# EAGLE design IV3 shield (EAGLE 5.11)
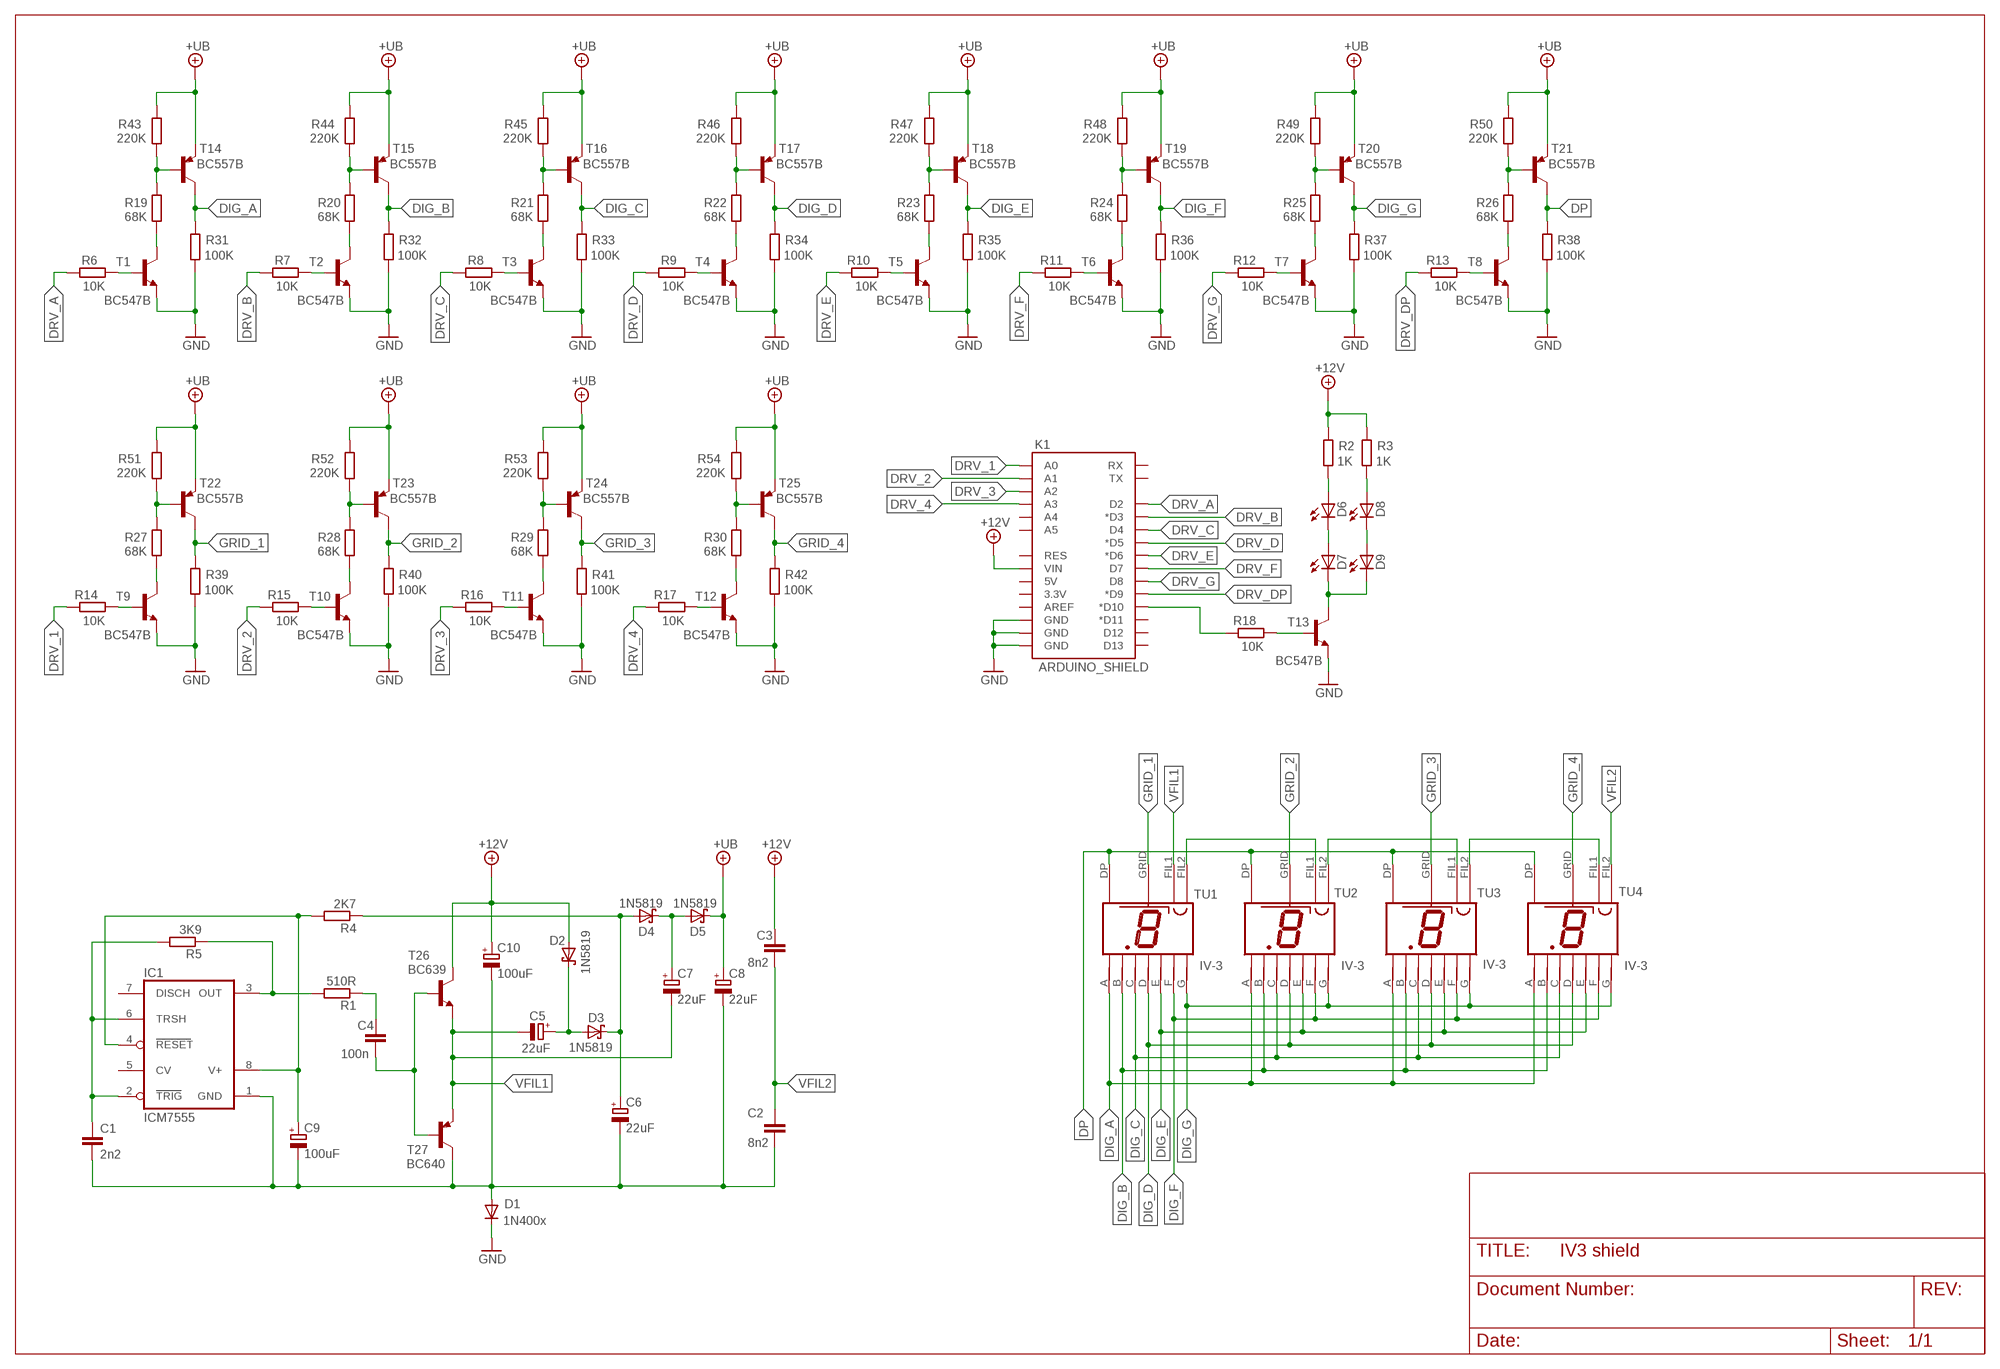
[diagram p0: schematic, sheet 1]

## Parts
C1  2n2  C5/2.5  [C5B2.5]
C2  8n2  C5/2.5  [C5B2.5]
C3  8n2  C5/2.5  [C5B2.5]
C4  100n  C5/2.5  [C5B2.5]
C5  22uF  CPOL-EUE2-4H  [E2-4H]
C6  22uF  CPOL-EUE2-4H  [E2-4H]
C7  22uF  CPOL-EUE2-4H  [E2-4H]
C8  22uF  CPOL-EUE2-4H  [E2-4H]
C9  100uF  CPOL-EUE2,5-6H  [E2,5-6H]
C10  100uF  CPOL-EUE2,5-6H  [E2,5-6H]
D1  1N400x  1N4004DO41-7.6  [DO41-7.6]
D2  1N5819  1N5819-B  [DO41-7.6]
D3  1N5819  1N5819-B  [DO41-7.6]
D4  1N5819  1N5819-B  [DO41-7.6]
D5  1N5819  1N5819-B  [DO41-7.6]
D6  LED3MM  [LED3MM]
D7  LED3MM  [LED3MM]
D8  LED3MM  [LED3MM]
D9  LED3MM  [LED3MM]
IC1  ICM7555  [DIL08]
K1  ARDUINO_SHIELD  ARDUINO_SHIELDNO_SILK  [DUEMILANOVE_VIAS]
R1  510R  R-EU_0207/2V  [0207/2V]
R2  1K  R-EU_0207/2V  [0207/2V]
R3  1K  R-EU_0207/2V  [0207/2V]
R4  2K7  R-EU_0207/2V  [0207/2V]
R5  3K9  R-EU_0207/2V  [0207/2V]
R6  10K  R-EU_0207/2V  [0207/2V]
R7  10K  R-EU_0207/2V  [0207/2V]
R8  10K  R-EU_0207/2V  [0207/2V]
R9  10K  R-EU_0207/2V  [0207/2V]
R10  10K  R-EU_0207/2V  [0207/2V]
R11  10K  R-EU_0207/2V  [0207/2V]
R12  10K  R-EU_0207/2V  [0207/2V]
R13  10K  R-EU_0207/2V  [0207/2V]
R14  10K  R-EU_0207/2V  [0207/2V]
R15  10K  R-EU_0207/2V  [0207/2V]
R16  10K  R-EU_0207/2V  [0207/2V]
R17  10K  R-EU_0207/2V  [0207/2V]
R18  10K  R-EU_0207/2V  [0207/2V]
R19  68K  R-EU_0207/2V  [0207/2V]
R20  68K  R-EU_0207/2V  [0207/2V]
R21  68K  R-EU_0207/2V  [0207/2V]
R22  68K  R-EU_0207/2V  [0207/2V]
R23  68K  R-EU_0207/2V  [0207/2V]
R24  68K  R-EU_0207/2V  [0207/2V]
R25  68K  R-EU_0207/2V  [0207/2V]
R26  68K  R-EU_0207/2V  [0207/2V]
R27  68K  R-EU_0207/2V  [0207/2V]
R28  68K  R-EU_0207/2V  [0207/2V]
R29  68K  R-EU_0207/2V  [0207/2V]
R30  68K  R-EU_0207/2V  [0207/2V]
R31  100K  R-EU_0207/2V  [0207/2V]
R32  100K  R-EU_0207/2V  [0207/2V]
R33  100K  R-EU_0207/2V  [0207/2V]
R34  100K  R-EU_0207/2V  [0207/2V]
R35  100K  R-EU_0207/2V  [0207/2V]
R36  100K  R-EU_0207/2V  [0207/2V]
R37  100K  R-EU_0207/2V  [0207/2V]
R38  100K  R-EU_0207/2V  [0207/2V]
R39  100K  R-EU_0207/2V  [0207/2V]
R40  100K  R-EU_0207/2V  [0207/2V]
R41  100K  R-EU_0207/2V  [0207/2V]
R42  100K  R-EU_0207/2V  [0207/2V]
R43  220K  R-EU_0207/2V  [0207/2V]
R44  220K  R-EU_0207/2V  [0207/2V]
R45  220K  R-EU_0207/2V  [0207/2V]
R46  220K  R-EU_0207/2V  [0207/2V]
R47  220K  R-EU_0207/2V  [0207/2V]
R48  220K  R-EU_0207/2V  [0207/2V]
R49  220K  R-EU_0207/2V  [0207/2V]
R50  220K  R-EU_0207/2V  [0207/2V]
R51  220K  R-EU_0207/2V  [0207/2V]
R52  220K  R-EU_0207/2V  [0207/2V]
R53  220K  R-EU_0207/2V  [0207/2V]
R54  220K  R-EU_0207/2V  [0207/2V]
T1  BC547B  BC547B-NPN-TO92-CBE  [TO92-CBE]
T2  BC547B  BC547B-NPN-TO92-CBE  [TO92-CBE]
T3  BC547B  BC547B-NPN-TO92-CBE  [TO92-CBE]
T4  BC547B  BC547B-NPN-TO92-CBE  [TO92-CBE]
T5  BC547B  BC547B-NPN-TO92-CBE  [TO92-CBE]
T6  BC547B  BC547B-NPN-TO92-CBE  [TO92-CBE]
T7  BC547B  BC547B-NPN-TO92-CBE  [TO92-CBE]
T8  BC547B  BC547B-NPN-TO92-CBE  [TO92-CBE]
T9  BC547B  BC547B-NPN-TO92-CBE  [TO92-CBE]
T10  BC547B  BC547B-NPN-TO92-CBE  [TO92-CBE]
T11  BC547B  BC547B-NPN-TO92-CBE  [TO92-CBE]
T12  BC547B  BC547B-NPN-TO92-CBE  [TO92-CBE]
T13  BC547B  BC547B-NPN-TO92-CBE  [TO92-CBE]
T14  BC557B  BC557B-PNP-TO92-EBC  [TO92-EBC]
T15  BC557B  BC557B-PNP-TO92-EBC  [TO92-EBC]
T16  BC557B  BC557B-PNP-TO92-EBC  [TO92-EBC]
T17  BC557B  BC557B-PNP-TO92-EBC  [TO92-EBC]
T18  BC557B  BC557B-PNP-TO92-EBC  [TO92-EBC]
T19  BC557B  BC557B-PNP-TO92-EBC  [TO92-EBC]
T20  BC557B  BC557B-PNP-TO92-EBC  [TO92-EBC]
T21  BC557B  BC557B-PNP-TO92-EBC  [TO92-EBC]
T22  BC557B  BC557B-PNP-TO92-EBC  [TO92-EBC]
T23  BC557B  BC557B-PNP-TO92-EBC  [TO92-EBC]
T24  BC557B  BC557B-PNP-TO92-EBC  [TO92-EBC]
T25  BC557B  BC557B-PNP-TO92-EBC  [TO92-EBC]
T26  BC639  BC639-NPN-TO92-ECB  [TO92-ECB]
T27  BC640  BC640-PNP-TO92-ECB  [TO92-ECB]
TU1  IV-3  [IV-3-WIDE]
TU2  IV-3  [IV-3-WIDE]
TU3  IV-3  [IV-3-WIDE]
TU4  IV-3  [IV-3-WIDE]

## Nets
+12V: C3.1 C10.+ D2.A K1.VIN R2.1 R3.1 T26.C
+UB: C8.+ D5.C R43.1 R44.1 R45.1 R46.1 R47.1 R48.1 R49.1 R50.1 R51.1 R52.1 R53.1 R54.1 T14.E T15.E T16.E T17.E T18.E T19.E T20.E T21.E T22.E T23.E T24.E T25.E
DIG_A: R31.1 T14.C TU1.A TU2.A TU3.A TU4.A
DIG_B: R32.1 T15.C TU1.B TU2.B TU3.B TU4.B
DIG_C: R33.1 T16.C TU1.C TU2.C TU3.C TU4.C
DIG_D: R34.1 T17.C TU1.D TU2.D TU3.D TU4.D
DIG_E: R35.1 T18.C TU1.E TU2.E TU3.E TU4.E
DIG_F: R36.1 T19.C TU1.F TU2.F TU3.F TU4.F
DIG_G: R37.1 T20.C TU1.G TU2.G TU3.G TU4.G
DP: R38.1 T21.C TU1.DP TU2.DP TU3.DP TU4.DP
DRV_1: K1.A0 R14.2
DRV_2: K1.A1 R15.2
DRV_3: K1.A2 R16.2
DRV_4: K1.A3 R17.2
DRV_A: K1.D2 R6.2
DRV_B: K1.D3(*D3) R7.2
DRV_C: K1.D4 R8.2
DRV_D: K1.D5(*D5) R9.2
DRV_DP: K1.D9(*D9) R13.2
DRV_E: K1.D6(*D6) R10.2
DRV_F: K1.D7 R11.2
DRV_G: K1.D8 R12.2
GND: D1.C K1.GND@0(GND) K1.GND@1(GND) K1.GND@2(GND) R31.2 R32.2 R33.2 R34.2 R35.2 R36.2 R37.2 R38.2 R39.2 R40.2 R41.2 R42.2 T1.E T2.E T3.E T4.E T5.E T6.E T7.E T8.E T9.E T10.E T11.E T12.E T13.E
GRID_1: R39.1 T22.C TU1.GRID
GRID_2: R40.1 T23.C TU2.GRID
GRID_3: R41.1 T24.C TU3.GRID
GRID_4: R42.1 T25.C TU4.GRID
N$1: C1.1 IC1.2(TRIG) IC1.6(TRSH) R5.2
N$2: IC1.3(OUT) R1.2 R5.1
N$3: C9.+ IC1.4(RESET) IC1.8(V+) R4.2
N$4: C1.2 C2.2 C6.- C8.- C9.- C10.- D1.A IC1.1(GND) T27.C
N$5: K1.D10(*D10) R18.2
N$6: C4.1 R1.1
N$7: C4.2 T26.B T27.B
N$8: R27.1 R51.2 T22.B
N$9: R19.1 R43.2 T14.B
N$10: R19.2 T1.C
N$11: R6.1 T1.B
N$12: C5.+ D2.C D3.A
N$13: C6.+ D3.C D4.A R4.1
N$14: R27.2 T9.C
N$15: C7.+ D4.C D5.A
N$16: R14.1 T9.B
N$17: R20.1 R44.2 T15.B
N$18: R20.2 T2.C
N$19: R7.1 T2.B
N$20: R21.1 R45.2 T16.B
N$21: R21.2 T3.C
N$22: R8.1 T3.B
N$23: R22.1 R46.2 T17.B
N$24: R22.2 T4.C
N$25: R9.1 T4.B
N$26: R23.1 R47.2 T18.B
N$27: R23.2 T5.C
N$28: R10.1 T5.B
N$29: R24.1 R48.2 T19.B
N$30: R24.2 T6.C
N$31: R11.1 T6.B
N$32: R25.1 R49.2 T20.B
N$33: R25.2 T7.C
N$34: R12.1 T7.B
N$35: R26.1 R50.2 T21.B
N$36: R26.2 T8.C
N$37: R13.1 T8.B
N$38: R28.1 R52.2 T23.B
N$39: R28.2 T10.C
N$40: R15.1 T10.B
N$41: R29.1 R53.2 T24.B
N$42: R29.2 T11.C
N$43: R16.1 T11.B
N$44: R30.1 R54.2 T25.B
N$45: R30.2 T12.C
N$46: R17.1 T12.B
N$47: R18.1 T13.B
N$49: D6.A R2.2
N$50: D8.A R3.2
N$51: D6.K(C) D7.A
N$52: D8.K(C) D9.A
N$53: D7.K(C) D9.K(C) T13.C
N$62: TU3.FIL2 TU4.FIL1
N$63: TU2.FIL2 TU3.FIL1
N$64: TU1.FIL2 TU2.FIL1
VFIL1: C5.- C7.- T26.E T27.E TU1.FIL1
VFIL2: C2.1 C3.2 TU4.FIL2
Unconnected: IC1.5(CV) IC1.7(DISCH) K1.3.3V K1.5V K1.A4 K1.A5 K1.AREF K1.D11(*D11) K1.D12 K1.D13 K1.RES K1.RX K1.TX

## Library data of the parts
C1-C4 = capacitor-wima:C: CAPACITOR
C5-C10 = rcl:CPOL-EU: POLARIZED CAPACITOR, European symbol
D1 = diode:1N4004: DIODE
D2-D5 = diode:1N581*: 1.0A SCHOTTKY BARRIER RECTIFIER
D6-D9 = led:LED: LED
IC1 = maxim:ICM7555: TIMER; MF: MAXIM; MPN: ICM7555IPA+; OC_FARNELL: 9663762; OC_NEWARK: 68K4387
K1 = SparkFun:ARDUINO_SHIELD
R1-R54 = rcl:R-EU_: RESISTOR, European symbol
T1-T13 T26 = transistor:*-NPN-: NPN Transistror BF959 corrected 2008.03.06
T14-T25 T27 = transistor:*-PNP-: PNP Transistror
TU1-TU4 = axiris_01:IV-3

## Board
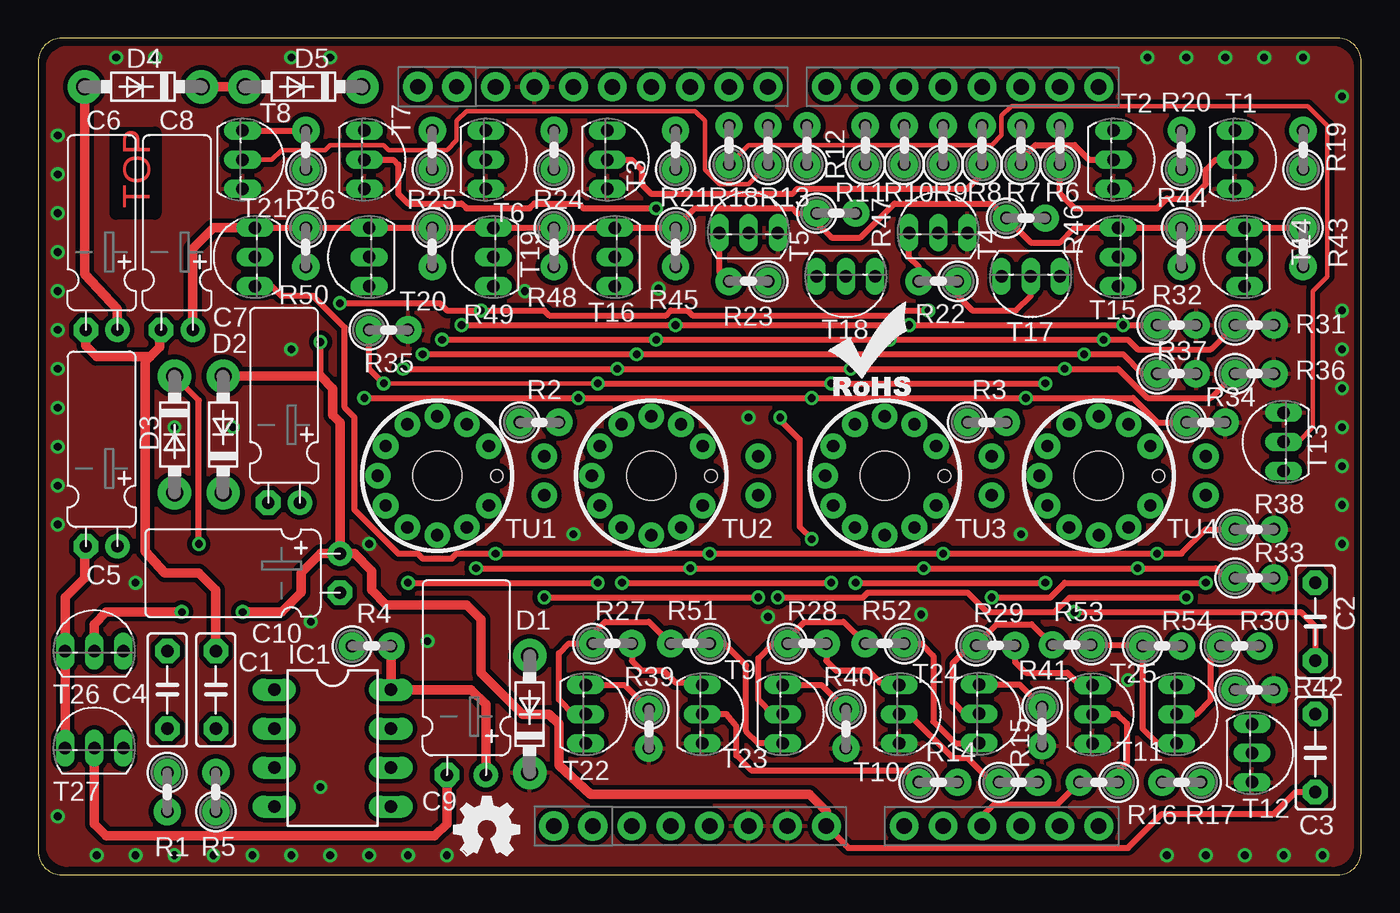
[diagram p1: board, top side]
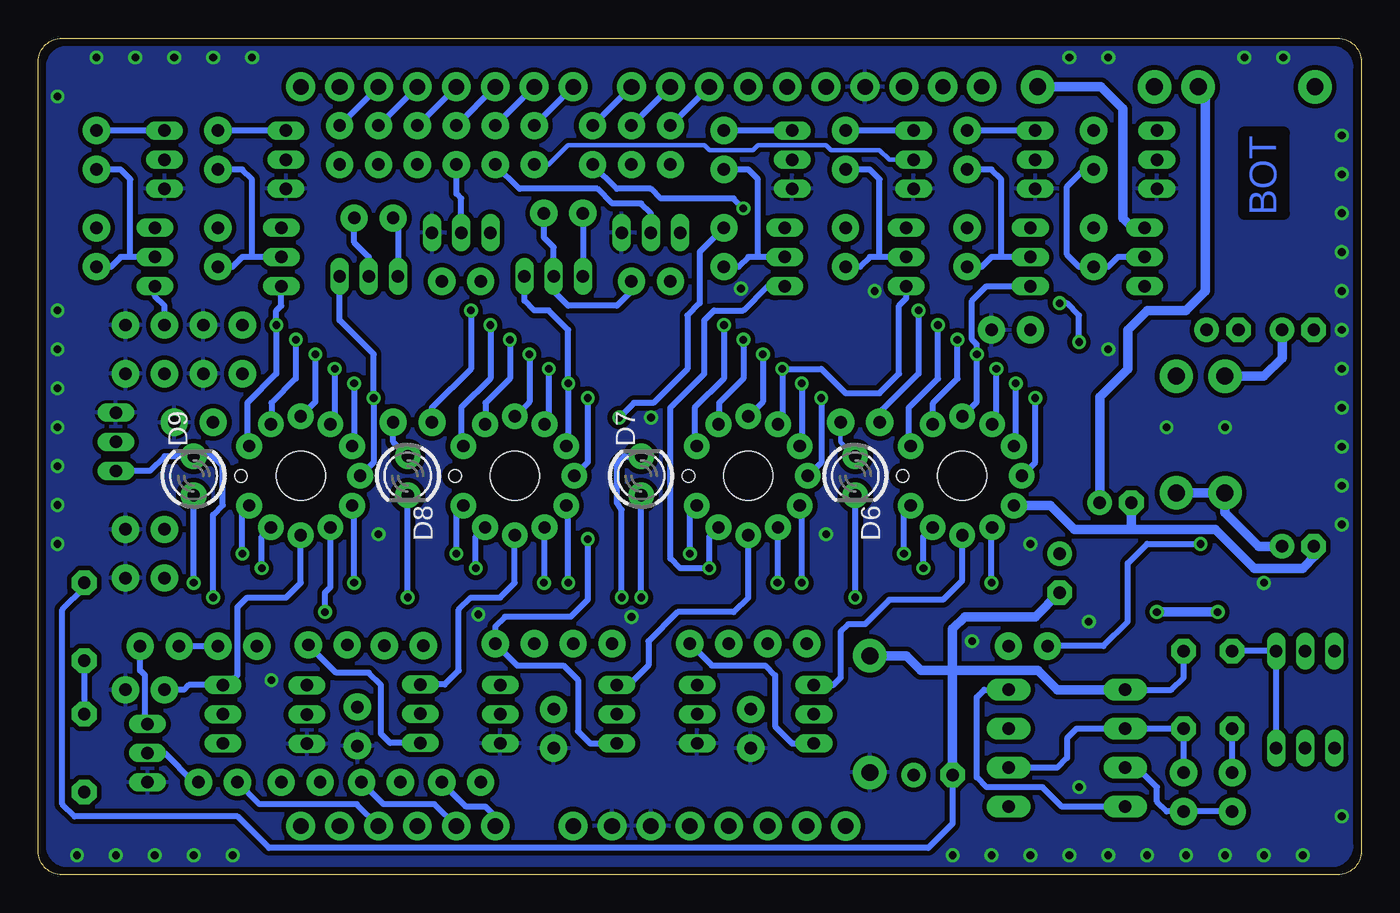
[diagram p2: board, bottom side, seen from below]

Size 86.34 x 54.6 mm. Coordinates in mm from the lower left corner, seen from the top.
Outline: 84.82,0 arc90 86.34,1.52 86.34,53.07 arc90 84.82,54.6 1.52,54.6 arc90 0,53.07 0,1.52 arc90 1.52,0 84.82,0
Copper layers (1*16): Top 0.018mm / dielectric 1.55mm / Bottom 0.018mm
Design rules "eC-STANDARD_pool-2-layer  *": minimum track width 0.15mm, minimum drill 0.25mm, track to track 0.15mm, track to pad 0.15mm, pad to pad 0.15mm, via to via 0.15mm, smd to smd 0.15mm, copper to edge 0.45mm, drill to drill 0.3mm, minimum pad ring 0.2mm, minimum via ring 0.2mm, stop-mask expansion 0.1mm, vias tented up to drill 20mil, thermal gap 0.2mm
Holes 3.2 mm at 26.04,26.04 40.01,26.04 55.24,26.04 69.22,26.04
tRestrict: 4 lines
bRestrict: 4 lines

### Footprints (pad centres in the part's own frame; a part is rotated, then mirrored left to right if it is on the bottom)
C5B2.5 = drill 0.813 pad 1.6 octagon: 1 -2.54,0; 2 2.54,0
E2-4H = drill 0.813 pad 1.6 round: + 0,1.032 | drill 0.813 pad 1.6 octagon: - 0,-1.032
E2,5-6H = drill 0.813 pad 1.6 round: + 0,1.27 | drill 0.813 pad 1.6 octagon: - 0,-1.27
DO41-7.6 = drill 1.1 pad 2.184 round: A 3.81,0; C -3.81,0
LED3MM = drill 0.813 pad 1.676 round: A -1.27,0; K 1.27,0
DIL08 = drill 0.813 pad 1.422 long: 1 -3.81,-3.81; 2 -1.27,-3.81; 3 1.27,-3.81; 4 3.81,-3.81; 5 3.81,3.81; 6 1.27,3.81; 7 -1.27,3.81; 8 -3.81,3.81
DUEMILANOVE_VIAS = drill 1.016 pad 1.88 round: 3.3V 50.8,13.97; 5V 50.8,16.51; A0 50.8,29.21; A1 50.8,31.75; A2 50.8,34.29; A3 50.8,36.83; A4 50.8,39.37; A5 50.8,41.91; AREF 2.54,2.54; D2 2.54,36.83; D3 2.54,34.29; D4 2.54,31.75; D5 2.54,29.21; D6 2.54,26.67; D7 2.54,24.13; D8 2.54,20.32; D9 2.54,17.78; D10 2.54,15.24; D11 2.54,12.7; D12 2.54,10.16; D13 2.54,7.62; GND@0 50.8,19.05; GND@1 50.8,21.59; GND@2 2.54,5.08; RES 50.8,11.43; RX 2.54,41.91; TX 2.54,39.37; VIN 50.8,24.13
0207/2V = drill 0.813 pad 1.778 round: 1 -1.27,0; 2 1.27,0
TO92-CBE = drill 0.813 long: B 0,0; C -1.905,0; E 1.905,0
TO92-EBC = drill 0.813 long: B 0,-1.27; C 1.905,-1.27; E -1.905,-1.27
TO92-ECB = drill 0.813 long: B 1.905,0; C 0,0; E -1.905,0
IV-3-WIDE = drill 0.8 pad 1.676 round: A 1.941,3.362; B 3.362,1.941; C 1.941,-3.362; D -3.882,0; DP 3.362,-1.941; E -3.362,1.941; F -1.941,3.362; FIL1 -3.362,-1.941; FIL2 -1.941,-3.362; G 0,3.882; GRID 0,-3.882 | hole 0.8: 3.897,-0.001

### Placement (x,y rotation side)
C1  11.59,12.06 90 top
C2  83.34,16.51 90 top
C3  83.34,7.94 90 top
C4  8.41,12.07 90 top
C5  4.13,21.43 270 top
C6  4.13,35.56 270 top
C7  16.03,24.29 270 top
C8  9.05,35.56 270 top
C9  27.94,6.51 270 top
C10  19.68,19.68 0 top
D1  32.07,10.48 90 top
D2  12.07,28.73 90 top
D3  8.89,28.73 270 top
D4  6.83,51.44 180 top
D5  17.3,51.43 180 top
D6  33.02,26.04 270 bottom
D7  46.99,26.04 90 bottom
D8  62.23,26.04 270 bottom
D9  76.2,26.04 90 bottom
IC1  19.21,8.26 270 top
K1  27.3,53.98 270 top
R1  8.41,5.4 270 top
R2  32.7,29.53 0 top
R3  61.91,29.53 0 top
R4  21.75,14.92 0 top
R5  11.59,5.4 90 top
R6  66.67,47.62 90 top
R7  64.14,47.62 90 top
R8  61.59,47.62 90 top
R9  59.05,47.62 90 top
R10  56.52,47.62 90 top
R11  53.98,47.62 90 top
R12  50.16,47.62 90 top
R13  47.62,47.62 90 top
R14  58.74,6.03 0 top
R15  63.98,6.03 0 top
R16  69.22,6.03 180 top
R17  74.61,6.03 180 top
R18  45.09,47.62 90 top
R19  82.55,47.31 90 top
R20  74.61,47.31 90 top
R21  41.59,47.31 90 top
R22  58.74,38.73 180 top
R23  46.35,38.73 180 top
R24  33.66,47.31 90 top
R25  25.72,47.31 90 top
R26  17.46,47.31 90 top
R27  37.47,15.08 0 top
R28  50.16,15.08 0 top
R29  62.48,14.95 0 top
R30  78.42,14.92 0 top
R31  79.38,35.88 0 top
R32  74.3,35.88 0 top
R33  79.38,19.37 0 top
R34  76.2,29.53 0 top
R35  22.86,35.56 0 top
R36  79.38,32.7 0 top
R37  74.3,32.7 0 top
R38  79.38,22.54 0 top
R39  39.85,9.53 270 top
R40  52.7,9.53 270 top
R41  65.51,9.68 270 top
R42  79.38,12.06 0 top
R43  82.55,40.96 270 top
R44  74.61,40.96 270 top
R45  41.59,40.96 270 top
R46  64.45,42.86 0 top
R47  52.07,43.18 0 top
R48  33.66,40.96 270 top
R49  25.72,40.96 270 top
R50  17.46,40.96 270 top
R51  42.55,15.08 180 top
R52  55.24,15.08 180 top
R53  67.45,15 180 top
R54  73.34,14.92 0 top
T1  78.11,46.67 270 top
T2  70.17,46.67 270 top
T3  37.15,46.67 270 top
T4  58.74,41.91 0 top
T5  46.35,41.91 0 top
T6  29.21,46.67 270 top
T7  21.27,46.67 270 top
T8  13.34,46.67 270 top
T9  43.34,10.48 270 top
T10  56.2,10.48 270 top
T11  68.81,10.46 270 top
T12  79.22,7.94 270 top
T13  81.28,28.26 90 top
T14  80.01,40.32 270 top
T15  71.75,40.32 270 top
T16  38.89,40.32 270 top
T17  64.77,40.32 0 top
T18  52.7,40.32 0 top
T19  30.96,40.32 270 top
T20  22.86,40.32 270 top
T21  15.4,40.32 270 top
T22  34.45,10.48 90 top
T23  47.31,10.48 90 top
T24  60.14,10.51 90 top
T25  73.03,10.48 90 top
T26  3.65,14.6 0 top
T27  3.65,8.26 0 top
TU1  26.04,26.04 0 top
TU2  40.01,26.04 0 top
TU3  55.24,26.04 0 top
TU4  69.22,26.04 0 top
U$1  [OSHW_FILLX150_NOTEXT]  27.15,1.27 0 top
U$2  [ROHS_SILK]  53.66,33.66 0 top

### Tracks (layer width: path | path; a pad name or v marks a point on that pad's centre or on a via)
+12V  (via drill 0.5)
  Top 0.406: v58.1,36.83 56.36,36.83 56.04,36.51 42.7,36.51 42.39,36.83 41.27,36.83 40.96,36.51 33.34,36.51 33.02,36.83 v28.89,36.83 26.67,36.83 26.19,37.31 v19.68,37.31 | K1.VIN 52.7,1.91 | 52.7,1.91 | 52.7,1.91 52.86,1.75 71.12,1.75 73.34,3.97 80.64,3.97 82.07,5.4 C3.1 | 18.41,32.54 v18.41,34.77
  Top 0.61: T26.C 3.65,16.35 4.45,17.14 v9.37,17.14 | C10.+ 18.41,20.95 17.14,19.68 17.14,18.41 15.88,17.14 v13.34,17.14 | C10.+ 19.68,29.53 19.21,30 19.21,31.75 18.41,32.54 D2.A | D2.A | K1.VIN 51.44,4.13 50.32,5.24 36.04,5.24 33.97,7.14 33.97,9.84 33.34,10.48 31.59,10.48 28.89,13.18 28.89,16.67 27.94,17.62 22.7,17.62 21.75,18.57 21.75,19.84 20.64,20.95 C10.+
  Bottom 0.406: R3.1 60.64,30.48 58.1,33.02 v58.1,36.83 | v28.89,36.83 28.89,32.7 31.43,30.16 R2.1 | v18.41,34.77 18.41,36.51 19.21,37.31 v19.68,37.31 | v19.68,37.31
  Bottom 0.61: v9.37,17.14 v13.34,17.14
+UB  (via drill 0.5)
  Top 0.406: R43.1 T14.E R44.1 T15.E 67.63,42.23 66.67,41.27 64.77,41.27 R46.1 62.23,43.81 55.88,43.81 53.66,41.59 51.75,41.59 50.8,42.55 R47.1 49.53,43.18 49.21,43.5 42.86,43.5 R45.1 T16.E R48.1 T19.E R49.1 T20.E R50.1 T21.E | T25.E 73.03,8.57 72.07,9.53 R54.1 72,15 R53.1 | R52.1 57.63,15.08 58.42,14.29 58.42,10 59.85,8.57 62.18,8.57 T24.E | R51.1 44.77,15.08 46.2,13.65 46.2,9.37 46.99,8.57 49.37,8.57 T23.E | v48.42,29.84 48.42,29.69 49.69,28.42 49.69,22.7 v50.48,21.91
  Top 0.61: C8.+ 10.08,40.88 11.43,42.23 T21.E
  Bottom 0.406: T17.E 62.87,42.55 R46.1 | R47.1 T18.E | T24.E 63.37,8.6 63.98,9.21 63.98,12.38 64.77,13.18 66.9,13.18 R53.1 | T23.E 50.32,8.57 51.12,9.37 51.12,12.7 52.07,13.65 55.09,13.65 R52.1 56.52,16.19 55.88,16.83 51.59,16.83 50.48,17.94 v50.48,21.91 | T22.E 37.15,8.57 38.26,9.68 38.26,13.02 38.89,13.65 42.39,13.65 R51.1 | R45.1 43.18,40.64 43.18,37.31 43.97,36.51 43.97,33.02 46.2,30.8 47.47,30.8 v48.42,29.84
  Bottom 0.61: D5.C 16.99,51.44 15.56,50.01 15.56,42.86 14.92,42.23 T21.E
DIG_A  (via drill 0.5)
  Top 0.406: v26.35,34.92 v40.32,34.92 v55.56,34.92 v69.53,34.92 71.12,34.92 71.75,34.29 76.52,34.29 R31.1
  Bottom 0.305: 71.12,29.43 TU4.A
  Bottom 0.406: v26.35,34.92 26.35,32.38 27.94,30.8 27.94,29.43 TU1.A | v40.32,34.92 40.32,32.38 41.91,30.8 41.91,29.43 TU2.A | v55.56,34.92 55.56,32.38 57.15,30.8 57.15,29.43 TU3.A | v69.53,34.92 69.53,32.38 71.12,30.8 71.12,29.43 | R31.1 78.11,37.15 78.74,37.78 T14.C
DIG_B  (via drill 0.5)
  Top 0.406: v27.62,35.88 v41.59,35.88 v56.83,35.88 v70.8,35.88 R32.1
  Bottom 0.406: v27.62,35.88 27.62,32.38 29.53,30.48 29.53,28.16 TU1.B | v41.59,35.88 41.59,32.38 43.5,30.48 43.5,28.11 TU2.B | v56.83,35.88 56.83,32.38 58.74,30.48 58.74,28.11 TU3.B | TU4.B 72.71,28.11 72.71,30.8 70.8,32.7 v70.8,35.88 70.8,36.83 70.48,37.15 T15.C
DIG_C  (via drill 0.5)
  Top 0.406: v28.57,20 v42.55,20 v57.78,20 v71.75,20 76.83,20 77.47,19.37 R33.1
  Bottom 0.406: v28.57,20 28.57,22.07 TU1.C | TU2.C 42.55,22.07 v42.55,20 44.45,20 45.09,20.64 45.09,30.48 42.86,32.7 42.86,36.2 42.23,36.83 40.32,36.83 38.73,38.42 T16.C | v57.78,20 57.78,22.07 TU3.C | v71.75,20 71.75,22.07 TU4.C
DIG_D  (via drill 0.5)
  Top 0.406: v21.27,31.11 v35.24,31.11 v50.48,31.11 v64.45,31.11 71.44,31.11 73.03,29.53 R34.1
  Bottom 0.406: v21.27,31.11 21.27,26.91 TU1.D | v35.24,31.11 35.24,26.91 TU2.D | v50.48,31.11 50.48,26.91 TU3.D | TU4.D 64.45,26.91 v64.45,31.11 64.45,33.97 66.67,36.2 T17.C
DIG_E  (via drill 0.5)
  Top 0.305: v22.54,32.07 v36.51,32.07
  Top 0.406: v36.51,32.07 v51.75,32.07 v65.72,32.07 | R35.1 21.59,33.02 v22.54,32.07
  Bottom 0.406: v22.54,32.07 22.54,28.11 TU1.E | v36.51,32.07 36.51,28.11 TU2.E | TU3.E 51.75,28.11 v51.75,32.07 51.75,35.56 53.02,36.83 53.98,36.83 54.61,37.47 T18.C | v65.72,32.07 65.72,28.11 TU4.E
DIG_F  (via drill 0.5)
  Top 0.406: v23.81,33.02 v37.78,33.02 v53.02,33.02 v66.99,33.02 70.48,33.02 72.39,31.11 76.52,31.11 R36.1
  Bottom 0.406: v23.81,33.02 23.81,29.68 TU1.F | TU2.F 37.78,29.68 v37.78,33.02 35.24,33.02 33.66,31.43 31.43,31.43 30.16,32.7 30.16,37.15 29.69,37.62 T19.C | v53.02,33.02 53.02,29.68 TU3.F | v66.99,33.02 66.99,29.68 TU4.F
DIG_G  (via drill 0.5)
  Top 0.406: v25.08,33.97 v39.05,33.97 v54.29,33.97 v68.26,33.97 70.8,33.97 72.07,32.7 R37.1
  Bottom 0.406: TU1.G 25.08,30.87 v25.08,33.97 25.08,34.61 25.4,34.92 25.4,37.47 24.45,38.42 T20.C | v39.05,33.97 39.05,30.87 TU2.G | v54.29,33.97 54.29,30.87 TU3.G | v68.26,33.97 68.26,30.87 TU4.G
DP  (via drill 0.5)
  Top 0.406: R38.1 76.2,22.54 74.61,20.95 v73.03,20.95 v59.05,20.95 v43.81,20.95 v29.84,20.95 27.3,20.95 26.99,20.64 25.08,20.64 24.77,20.95 23.5,20.95 20.64,23.81 20.64,29.84 20,30.48 20,35.72 17.94,37.78 15.88,37.78 15.24,38.42 T21.C
  Bottom 0.406: v29.84,20.95 29.84,23.65 TU1.DP | v43.81,20.95 43.81,23.65 TU2.DP | v59.05,20.95 59.05,23.65 TU3.DP | v73.03,20.95 73.03,23.65 TU4.DP
DRV_1
  Bottom 0.406: K1.A0 56.52,3.81 57.15,4.45 58.42,4.45 R14.2
DRV_2
  Bottom 0.406: K1.A1 60.48,4.6 63.82,4.6 R15.2
DRV_3
  Top 0.406: K1.A2 61.59,3.81 62.39,4.6 66.52,4.6 R16.2
DRV_4
  Bottom 0.406: K1.A3 65.56,4.6 71.91,4.6 R17.2
DRV_A
  Bottom 0.406: K1.D2 R6.2
DRV_B
  Bottom 0.406: K1.D3 R7.2
DRV_C
  Bottom 0.406: K1.D4 R8.2
DRV_D
  Bottom 0.406: K1.D5 R9.2
DRV_DP
  Bottom 0.406: K1.D9 R13.2
DRV_E
  Bottom 0.406: K1.D6 R10.2
DRV_F
  Bottom 0.406: K1.D7 R11.2
DRV_G
  Bottom 0.406: K1.D8 R12.2
GND  (via drill 0.5)
  other vias: 34.92,22.23 46.35,29.84 64.14,22.23 71.12,12.7 18.41,5.71 25.4,15.24 31.75,38.1 40.48,38.26 47.62,16.83 57.63,16.99 21.59,21.59 16.51,34.29 6.35,19.05 17.78,16.51 8.89,29.21 12.7,29.21 1.27,3.81 26.67,1.27 24.13,1.27 21.59,1.27 19.05,1.27 16.51,1.27 13.97,1.27 11.43,1.27 8.89,1.27 6.35,1.27 3.81,1.27 73.66,1.27 76.2,1.27 78.74,1.27 81.28,1.27 83.82,1.27 85.09,21.59 85.09,24.13 85.09,26.67 85.09,29.21 85.09,31.75 85.09,34.29 85.09,36.83 85.09,50.8 82.55,53.34 80.01,53.34 77.47,53.34 74.93,53.34 72.39,53.34 5.08,53.34 7.62,53.34 16.51,53.34 19.05,53.34 1.27,48.26 1.27,45.72 1.27,43.18 1.27,40.64 1.27,38.1 1.27,35.56 1.27,33.02 1.27,30.48 1.27,27.94 1.27,25.4 1.27,22.86
  pour Top (isolate 0.305): 0.64,52.7 arc-90 1.91,53.98 84.45,53.98 arc-90 85.72,52.7 85.72,1.91 arc-90 84.45,0.64 1.91,0.64 arc-90 0.64,1.91
  pour Bottom (isolate 0.305): 0.64,52.7 arc-90 1.91,53.98 84.45,53.98 arc-90 85.72,52.7 85.72,1.91 arc-90 84.45,0.64 1.91,0.64 arc-90 0.64,1.91
GRID_1
  Top 0.406: T22.C 38.26,12.38 R39.1
  Bottom 0.406: T22.C 34.45,12.38 33.97,12.86 33.97,15.88 33.5,16.35 32.38,16.35 30.8,17.94 27.3,17.94 26.04,19.21 TU1.GRID
GRID_2
  Top 0.406: T23.C 51.12,12.38 R40.1
  Bottom 0.406: T23.C 47.78,12.38 46.51,13.65 46.51,15.24 44.61,17.14 40.96,17.14 40.01,18.1 TU2.GRID
GRID_3
  Top 0.406: T24.C 64.05,12.41 R41.1
  Bottom 0.406: T24.C 59.82,12.41 58.9,13.34 58.9,17.3 58.1,18.1 56.2,18.1 55.24,19.05 TU3.GRID
GRID_4
  Bottom 0.406: R42.1 76.83,12.06 76.52,12.38 T25.C 73.98,12.38 73.34,13.02 73.34,17.46 72.71,18.1 70.17,18.1 69.22,19.05 TU4.GRID
N$1
  Bottom 0.406: R5.2 C1.1 | C1.1 | C1.1 IC1.2 18.57,9.53 19.21,8.89 19.21,7.62 19.84,6.99 IC1.6
N$2
  Bottom 0.406: R1.2 R5.1 12.7,4.13 13.34,4.76 13.34,5.71 14.61,6.99 IC1.3
N$3
  Top 0.61: C9.+ 29.21,11.11 28.26,12.06 IC1.8 23.02,15.4 R4.2
  Bottom 0.406: IC1.4 19.53,4.45 20.8,5.71 24.45,5.71 25.08,6.35 25.08,11.59 24.61,12.06 IC1.8
N$4
  Top 0.61: T27.C 3.65,3.33 4.45,2.54 25.88,2.54 26.67,3.33 C9.- | C6.- 3.1,34.53 3.81,33.81 7.3,33.81 | 7.3,33.81 7.94,34.45 7.94,35.48 C8.- | C1.2 11.59,18.57 10.48,19.68 8.26,19.68 6.99,21.11 6.99,33.5 7.3,33.81
  Bottom 0.406: IC1.1 12.38,12.06 11.59,12.86 C1.2 | C1.2 | C2.2 83.34,18.73 84.77,17.3 84.77,4.6 83.98,3.81 73.34,3.81 71.28,1.75 28.26,1.75 26.67,3.33 C9.-
  Bottom 0.61: C9.- 26.67,13.34 | 26.67,13.34 21.11,13.34 19.84,12.06 IC1.1 | 26.67,13.34 26.67,16.03 25.88,16.83 21.27,16.83 C10.- | 26.67,13.34 28.73,13.34 29.69,14.29 D1.A
N$5
  Bottom 0.406: R18.2 K1.D10
N$6
  Bottom 0.406: R1.1 C4.1
N$7
  Bottom 0.406: T27.B T26.B C4.2 | C4.2
N$8
  Top 0.406: T22.B 34.92,10.48 33.97,11.43 33.97,14.45 34.61,15.08 R27.1 36.2,15.72 36.99,16.51 39.85,16.51 R51.2
N$9
  Bottom 0.406: T14.B 80.33,40.32 | 80.33,40.32 80.33,45.4 80.96,46.04 R19.1 | 80.33,40.32 80.96,40.32 81.6,39.69 R43.2
N$10
  Bottom 0.406: T1.C R19.2
N$11
  Top 0.406: R6.1 66.67,44.45 67.63,43.5 73.03,43.5 73.66,44.13 75.25,44.13 76.2,45.09 76.2,46.04 76.83,46.67 T1.B
N$12
  Bottom 0.61: D2.C D3.A 8.89,23.65 6.67,21.43 C5.+ | D2.C
N$13  (via drill 0.5)
  Top 0.406: v10.48,21.59 10.48,30.96 D3.C
  Top 0.61: C6.+ 5.16,36.91 3.02,39.21 | 3.02,39.21 D4.A | 3.02,39.21
  Bottom 0.406: R4.1 16.83,14.92 15.24,16.51 15.24,20.32 13.97,21.59 v10.48,21.59
  Bottom 0.61: C6.+ 5.16,33.73 6.35,32.54 D3.C
N$14
  Top 0.406: R27.2 38.73,13.97 39.37,13.34 40.8,13.34 41.59,12.54 43.18,12.54 T9.C
N$15
  Top 0.61: D4.C D5.A | D5.A
  Bottom 0.61: C7.+ 17.07,31.19 15.24,33.02 15.24,35.56 13.97,36.83 11.43,36.83 10.16,38.1 10.16,50.96 D4.C
N$16
  Top 0.406: T9.B 44.93,10.48 45.56,9.68 45.56,7.78 46.51,6.83 56.67,6.83 R14.1
N$17
  Bottom 0.406: T15.B 72.39,40.32 | 72.39,40.32 72.39,45.4 73.03,46.04 R20.1 | 72.39,40.32 73.03,40.32 73.66,39.69 R44.2
N$18
  Bottom 0.406: T2.C R20.2
N$19
  Top 0.406: R7.1 64.14,46.67 65.09,47.62 67.63,47.62 68.58,46.67 T2.B
N$20
  Bottom 0.406: T16.B 39.37,40.32 | 39.37,40.32 39.37,45.4 40.01,46.04 R21.1 | 39.37,40.32 40.01,40.32 40.64,39.69 R45.2
N$21
  Bottom 0.406: T3.C R21.2
N$22
  Top 0.406: R8.1 61.59,45.72 60.64,44.77 49.53,44.77 49.21,44.45 40.01,44.45 39.37,45.09 39.37,46.04 38.73,46.67 T3.B
N$23
  Top 0.406: R22.1 60.01,37.78 60.96,36.83 63.82,36.83 64.77,37.78 T17.B
  Bottom 0.406: T17.B 64.77,40.32 65.72,41.27 R46.2
N$24
  Top 0.406: R22.2 57.47,39.69 56.83,40.32 T4.C
N$25
  Bottom 0.406: T4.B 58.74,44.13 59.05,44.45 R9.1
N$26
  Bottom 0.406: R47.2 53.34,41.59 52.7,40.96 T18.B 52.7,38.1 51.75,37.15 48.58,37.15 47.62,38.1 R23.1
N$27
  Top 0.406: T5.C 44.45,39.37 R23.2
N$28
  Bottom 0.406: T5.B 46.35,43.18 46.99,43.81 48.9,43.81 49.85,44.77 54.93,44.77 R10.1
N$29
  Bottom 0.406: T19.B 31.43,40.32 | 31.43,40.32 31.43,45.4 32.07,46.04 R24.1 | 31.43,40.32 32.07,40.32 32.7,39.69 R48.2
N$30
  Bottom 0.406: T6.C R24.2
N$31
  Bottom 0.305: R11.1 53.02,46.35 51.75,47.62 42.86,47.62 42.55,47.31 39.69,47.31 39.37,47.62 34.92,47.62 34.61,47.31 31.43,47.31 30.8,46.67 T6.B
N$32
  Bottom 0.406: T20.B 23.5,40.32 | 23.5,40.32 23.5,45.4 24.13,46.04 R25.1 | 23.5,40.32 24.13,40.32 24.77,39.69 R49.2
N$33
  Bottom 0.406: T7.C R25.2
N$34  (via drill 0.5)
  Top 0.406: T7.B 23.18,46.67 23.5,46.35 23.5,44.45 24.13,43.81 27.62,43.81 27.94,43.5 32.07,43.5 32.38,43.81 35.24,43.81 35.56,43.5 v40.32,43.5
  Bottom 0.406: v40.32,43.5 40.96,44.13 45.72,44.13 46.35,44.77 48.58,44.77 R12.1
N$35
  Bottom 0.406: T21.B 15.88,40.32 16.51,39.69 R50.2 18.41,39.69 19.21,40.48 19.21,44.93 18.1,46.04 R26.1
N$36
  Top 0.406: T8.C R26.2
N$37
  Top 0.305: R13.1 46.35,45.09 44.45,45.09 43.5,46.04 43.5,49.21 42.86,49.85 27.94,49.85 27.3,49.21 27.3,47.94 26.67,47.31 22.86,47.31 22.54,47.62 19.05,47.62 18.73,47.31 15.88,47.31 15.24,46.67 T8.B
N$38
  Top 0.406: T23.B 47.94,10.48 46.99,11.43 46.99,14.13 47.94,15.08 R28.1 48.9,15.4 50.01,16.51 52.55,16.51 R52.2
N$39
  Top 0.406: R28.2 51.44,13.97 52.07,13.34 54.13,13.34 54.93,12.54 56.04,12.54 T10.C
N$40
  Top 0.406: T10.B 56.83,10.48 59.69,7.62 60.64,7.62 62.07,6.19 62.55,6.19 R15.1
N$41
  Top 0.406: T24.B 61.86,10.48 60.48,10.48 59.69,11.27 59.69,13.81 60.83,14.95 R29.1 61.21,15.02 62.55,16.35 64.83,16.35 R53.2
N$42
  Top 0.406: R29.2 63.75,13.88 64.45,13.18 67.15,13.18 67.79,12.54 68.63,12.54 T11.C
N$43
  Top 0.406: R16.1 70.48,6.78 71.07,7.36 71.07,9.85 70.44,10.48 70.37,10.48 T11.B
N$44
  Top 0.406: T25.B 75.56,10.48 76.52,11.43 76.52,14.29 R30.1
  Bottom 0.406: R30.1 R54.2
N$45
  Bottom 0.406: T12.C 79.22,10.16 79.38,10.32 79.38,13.02 79.69,13.34 R30.2
N$46
  Bottom 0.406: R17.1 76.2,6.03 78.11,7.94 T12.B
N$47
  Top 0.305: R18.1 46.35,47.62 62.23,47.62 62.87,48.26 62.87,49.53 63.5,50.16 82.87,50.16 84.14,48.9 84.14,39.05 83.19,38.1 83.19,29.21 82.23,28.26 T13.B
N$48  (via drill 1 pad 1.93)
  other vias: 36.2,3.17
N$49
  Bottom 0.305: D6.A 33.97,28.26 R2.2
N$50
  Bottom 0.406: D8.A 63.18,28.26 R3.2
N$51  (via drill 0.5)
  Top 0.406: v33.02,18.1 v46.99,18.1
  Bottom 0.406: v33.02,18.1 D6.K | v46.99,18.1 D7.A
N$52  (via drill 0.5)
  Top 0.406: v62.23,18.1 66.04,18.1 66.99,19.05 v76.2,19.05
  Bottom 0.406: v62.23,18.1 D8.K | v76.2,19.05 D9.A
N$53  (via drill 0.5)
  Top 0.406: v48.26,18.1 53.82,18.1 54.13,18.41 60.64,18.41 61.91,17.14 66.36,17.14 67.31,18.1 v74.93,18.1
  Bottom 0.406: v48.26,18.1 48.26,23.81 48.58,24.29 48.58,26.83 48.1,27.3 D7.K | v74.93,18.1 74.93,23.5 74.3,24.13 74.3,26.67 74.93,27.3 D9.K 78.11,27.3 79.06,26.35 T13.C
N$54  (via drill 1 pad 1.93)
  other vias: 33.66,3.17
N$55  (via drill 1 pad 1.93)
  other vias: 27.3,51.44
N$56  (via drill 1 pad 1.93)
  other vias: 24.77,51.44
N$62  (via drill 0.5)
  Top 0.406: v53.34,19.05 v65.72,19.05
  Bottom 0.406: v53.34,19.05 53.34,22.64 TU3.FIL2 | v65.72,19.05 65.72,23.96 TU4.FIL1
N$63  (via drill 0.5)
  Top 0.406: v38.1,19.05 v51.75,19.05
  Bottom 0.406: v38.1,19.05 38.1,22.64 TU2.FIL2 | v51.75,19.05 51.75,23.96 TU3.FIL1
N$64  (via drill 0.5)
  Top 0.406: v24.13,19.05 v36.51,19.05
  Bottom 0.305: 24.13,22.64 TU1.FIL2
  Bottom 0.406: v36.51,19.05 36.51,23.96 TU2.FIL1 | v24.13,19.05 24.13,22.64
VFIL1
  Top 0.61: T27.E T26.E 1.75,18.1 3.02,19.37 3.02,21.35 C5.-
  Bottom 0.61: 15,22.7 15,22.54 9.53,22.54 6.99,20 3.81,20 3.02,20.8 3.02,21.35 C5.- | 15,22.7 C7.- | TU1.FIL1 20.28,24.09 18.73,22.54 15.16,22.54 15,22.7
VFIL2  (via drill 0.5)
  Top 0.406: v67.63,17.14 82.39,17.14 83.34,16.19 C2.1
  Bottom 0.406: C2.1 C3.2 | TU4.FIL2 67.27,18.77 67.63,18.41 v67.63,17.14

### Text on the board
Top: TOP
Bottom: BOT
tDocu: Axiris | IV-3 shield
